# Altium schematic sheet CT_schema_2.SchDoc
size 383 x 329 mm
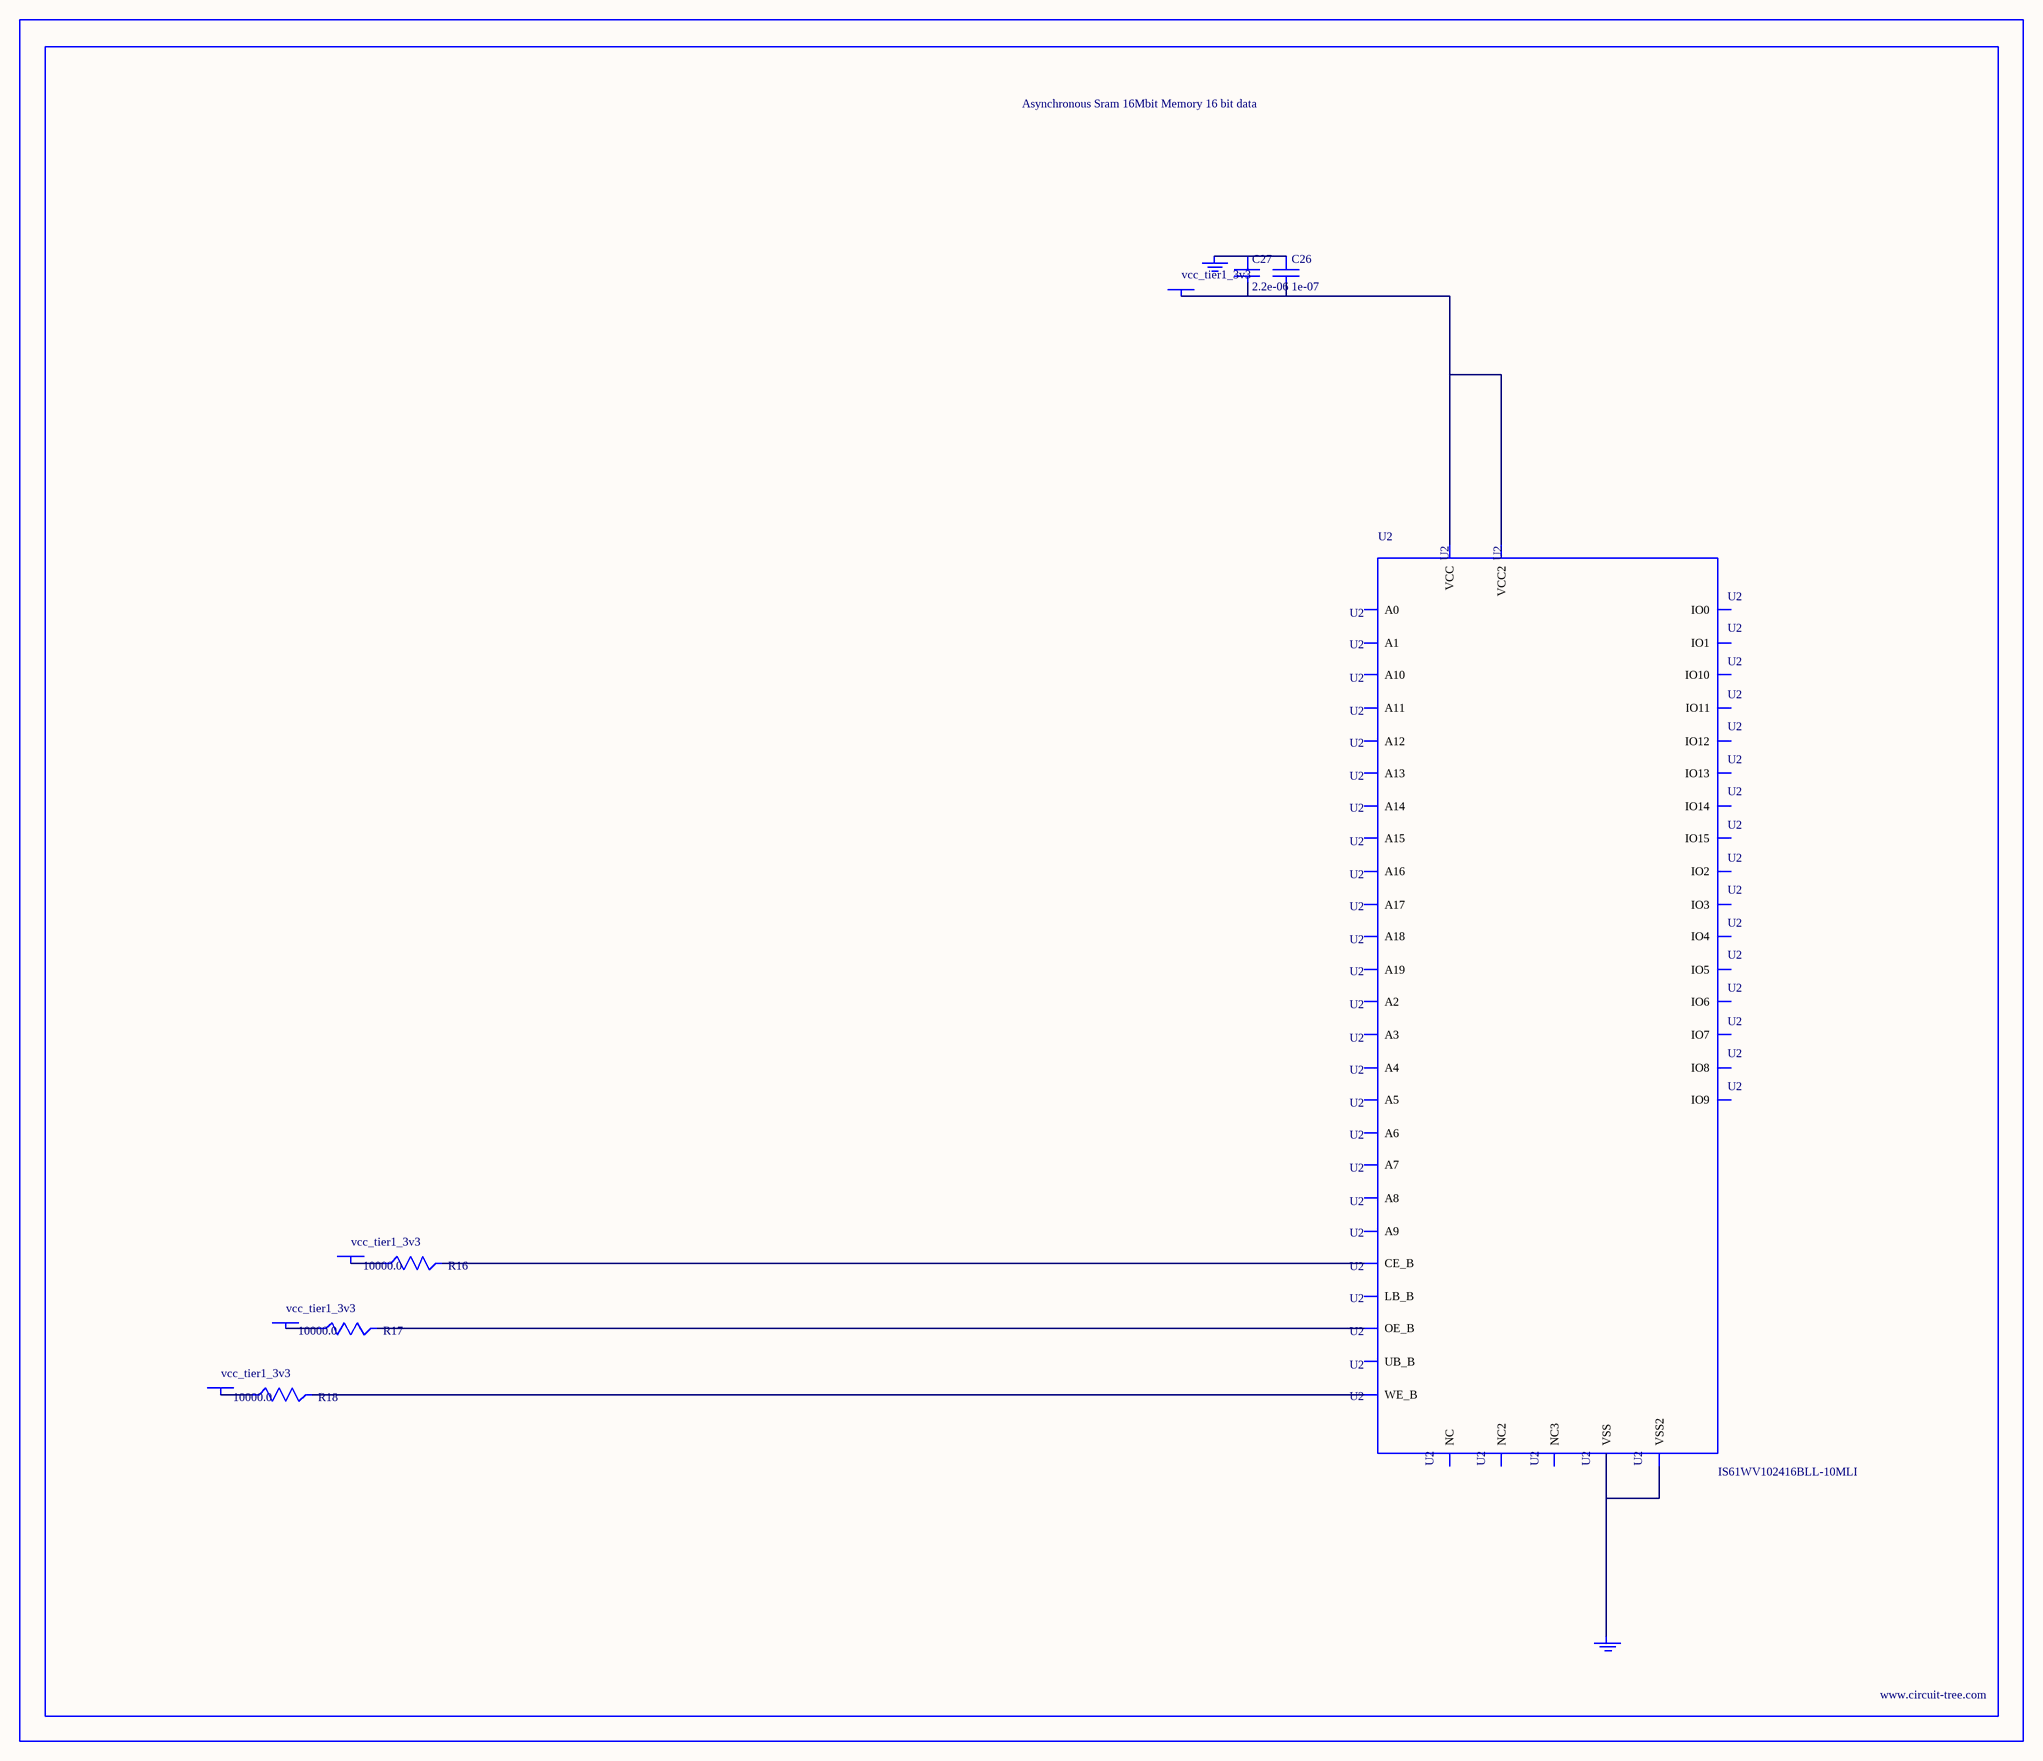
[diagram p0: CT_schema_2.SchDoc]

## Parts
BORDER1  (no value)
C26  1e-07  [C0402]
C27  2.2e-06  [C0603]
GND_INSTANCE_1_0  (no value)
GND_INSTANCE_1_1  (no value)
POWER_INSTANCE_1_0  vcc_tier1_3v3
POWER_INSTANCE_1_1  vcc_tier1_3v3
POWER_INSTANCE_1_2  vcc_tier1_3v3
POWER_INSTANCE_1_3  vcc_tier1_3v3
R16  10000.0  [R0603]
R17  10000.0  [R0603]
R18  10000.0  [R0603]
U2  IS61WV102416BLL-10MLI  [IS61WV102416BLL-10MLI]

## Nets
NetC26_1: C26.1 C27.1 GND_INSTANCE_1_0.0(GND)
NetC26_2: C26.2 C27.2 POWER_INSTANCE_1_0.0(PWR) U2.D6(VCC) U2.E1(VCC2)
NetGND_INSTANCE_1_1_0: GND_INSTANCE_1_1.0(GND) U2.D1(VSS) U2.E6(VSS2)
NetPOWER_INSTANCE_1_1_0: POWER_INSTANCE_1_1.0(PWR) R16.1
NetPOWER_INSTANCE_1_2_0: POWER_INSTANCE_1_2.0(PWR) R17.1
NetPOWER_INSTANCE_1_3_0: POWER_INSTANCE_1_3.0(PWR) R18.1
NetR16_2: R16.2 U2.B5(CE_B)
NetR17_2: R17.2 U2.A2(OE_B)
NetR18_2: R18.2 U2.G5(WE_B)

Not connected (* = marked no-connect by the designer): U2 A1(LB_B) A3(A0) A4(A1) A5(A2) A6(NC) B1(IO8) B2(UB_B) B3(A3) B4(A4) B6(IO0) C1(IO9) C2(IO10) C3(A5) C4(A6) C5(IO1) C6(IO2) D2(IO11) D3(A17) D4(A7) D5(IO3) E2(IO12) E3(NC2) E4(A16) E5(IO4) F1(IO14) F2(IO13) F3(A14) F4(A15) F5(IO5) F6(IO6) G1(IO15) G2(A19) G3(A12) G4(A13) G6(IO7) H1(A18) H2(A8) H3(A9) H4(A10) H5(A11) H6(NC3)

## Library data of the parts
BORDER1 = BORDER_PAGE1
C26 = C0402C104K3RACTU
C27 = C0603C225K8RACTU
GND_INSTANCE_1_0 GND_INSTANCE_1_1 = GND
POWER_INSTANCE_1_0-POWER_INSTANCE_1_3 = PWR
R16-R18 = RC0603JR-0710KL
